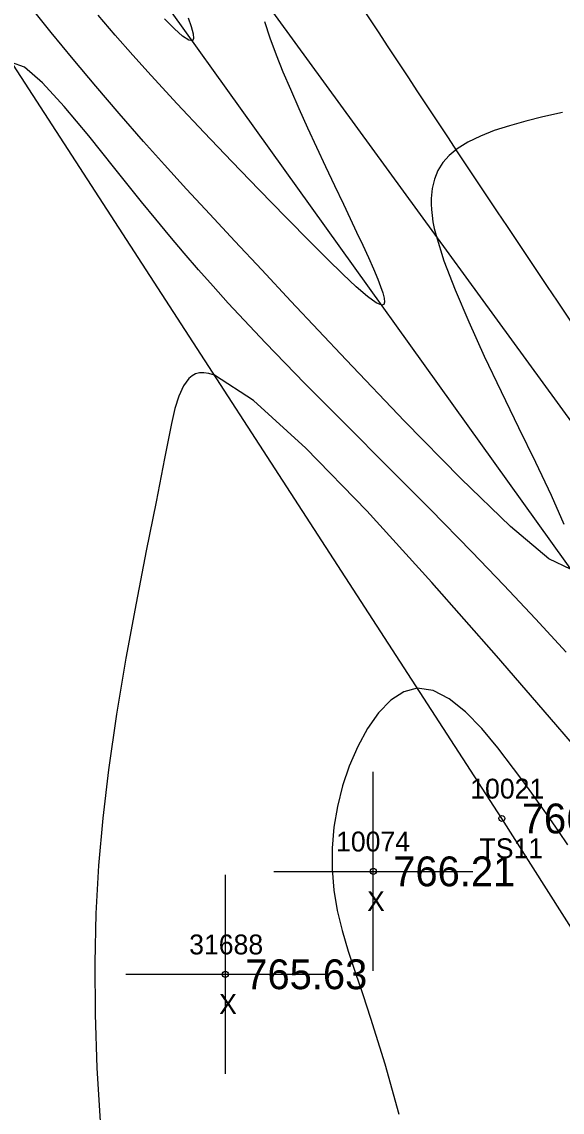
# Model space of a CAD drawing. Extents: x 1376587 to 1378239, y 1000335 to 1003031.
# Drawn here: x 1377991.7 to 1378018.9, y 1000532.4 to 1000587.3 of the extents above; entities that cross this region are included whole.
import ezdxf

# ---------------------------------------------------------------- set-up
doc = ezdxf.new("R2010")
doc.units = 0
for name, color, linetype in [('RD_DTM_BkLn1', 7, 'Continuous'), ('RD_DTM_BkLn2', 7, 'Continuous'), ('RD_DTM_BkLn_txCode', 7, 'Continuous'), ('RD_DTM_Major1', 7, 'Continuous'), ('RD_DTM_Minor1', 7, 'Continuous'), ('RD_EX_H2O', 7, 'Continuous'), ('RD_EX_Misc', 7, 'Continuous'), ('RD_EX_Misc_txCode', 7, 'Continuous'), ('RD_EX_Road', 7, 'Continuous'), ('RD_EX_TX_Misc_ELEV', 7, 'Continuous'), ('RD_SMD_Locator', 7, 'Continuous')]:
    doc.layers.add(name, color=color, linetype=linetype)

msp = doc.modelspace()

# ---------------------------------------------------------------- linework, layer by layer
at = {"layer": 'RD_DTM_BkLn1'}
msp.add_spline([(1378169.212, 1000387.103), (1378131.506, 1000434.744), (1378095.477, 1000481.988), (1378063.033, 1000526.867), (1378030.177, 1000574.233), (1377998.011, 1000622.539), (1377965.721, 1000673.201), (1377936, 1000721.493), (1377904.113, 1000773.429), (1377890.868, 1000795.129)], degree=3, dxfattribs=at)
at = {"layer": 'RD_DTM_BkLn2'}
for points in [[(1378152.795, 1000376.442), (1378153.623, 1000378.891), (1378133.341, 1000407.77), (1378106.208, 1000444.47), (1378079.422, 1000481.908), (1378052.603, 1000518.078), (1378027.38, 1000556.138), (1377999.887, 1000593.901), (1377975.443, 1000634.683), (1377966.188, 1000647.973)], [(1378152.458, 1000376.254), (1378150.255, 1000376.168), (1378128.245, 1000403.35), (1378101.014, 1000439.163), (1378072.773, 1000477.242), (1378039.24, 1000510.344), (1378015.855, 1000547.194), (1377989.301, 1000588.148), (1377962.727, 1000626.954), (1377952.76, 1000642.197)]]:
    msp.add_lwpolyline(points, dxfattribs=at)
at = {"layer": 'RD_DTM_Major1'}
msp.add_lwpolyline([(1378020.131, 1000550.114), (1378018.569, 1000551.921), (1378015.582, 1000555.372), (1378012.335, 1000559.066), (1378009.061, 1000562.665), (1378005.992, 1000565.828), (1378003.361, 1000568.216), (1378001.399, 1000569.489), (1378001.121, 1000569.577), (1378000.873, 1000569.616), (1378000.651, 1000569.608), (1378000.453, 1000569.555), (1378000.276, 1000569.46), (1378000.116, 1000569.325), (1377999.842, 1000568.95), (1377999.613, 1000568.44), (1377999.417, 1000567.809), (1377999.241, 1000567.067), (1377999.07, 1000566.227), (1377998.893, 1000565.301), (1377998.464, 1000563.114), (1377997.977, 1000560.665), (1377997.463, 1000558.023), (1377996.953, 1000555.258), (1377996.478, 1000552.439), (1377996.07, 1000549.634), (1377995.785, 1000547.215), (1377995.576, 1000544.82), (1377995.442, 1000542.406), (1377995.384, 1000539.931), (1377995.401, 1000537.355), (1377995.493, 1000534.634), (1377995.677, 1000531.698)], dxfattribs=at)
at = {"layer": 'RD_DTM_Minor1'}
for points in [[(1378019.341, 1000559.714), (1378018.219, 1000560.254), (1378016.287, 1000561.879), (1378013.785, 1000564.289), (1378010.951, 1000567.183), (1378008.027, 1000570.26), (1378005.249, 1000573.219), (1378003.777, 1000574.789), (1378002.422, 1000576.237), (1378001.166, 1000577.585), (1377999.993, 1000578.856), (1377998.886, 1000580.071), (1377997.83, 1000581.251), (1377996.608, 1000582.65), (1377995.43, 1000584.031), (1377994.294, 1000585.394), (1377993.195, 1000586.739), (1377992.128, 1000588.068)], [(1378003.917, 1000587.291), (1378004.189, 1000586.459), (1378004.502, 1000585.612), (1378004.847, 1000584.752), (1378005.218, 1000583.877), (1378005.64, 1000582.914), (1378006.079, 1000581.942), (1378006.528, 1000580.967), (1378006.982, 1000579.996), (1378007.436, 1000579.036), (1378007.884, 1000578.094), (1378008.223, 1000577.382), (1378008.549, 1000576.692), (1378008.856, 1000576.032), (1378009.14, 1000575.411), (1378009.393, 1000574.836), (1378009.61, 1000574.316), (1378009.752, 1000573.948), (1378009.861, 1000573.629), (1378009.929, 1000573.366), (1378009.949, 1000573.17), (1378009.915, 1000573.048), (1378009.819, 1000573.01), (1378009.532, 1000573.131), (1378009.095, 1000573.453), (1378008.528, 1000573.946), (1378007.853, 1000574.581), (1378007.091, 1000575.328), (1378006.262, 1000576.156), (1378004.987, 1000577.446), (1378003.647, 1000578.817), (1378002.271, 1000580.242), (1378000.889, 1000581.694), (1377999.529, 1000583.147), (1377998.221, 1000584.572), (1377997.302, 1000585.596), (1377996.415, 1000586.6), (1377995.548, 1000587.596)], [(1378000.076, 1000587.477), (1378000.231, 1000587.027), (1378000.328, 1000586.672), (1378000.353, 1000586.427), (1378000.296, 1000586.306), (1378000.108, 1000586.339), (1377999.799, 1000586.55), (1377999.386, 1000586.916), (1377998.887, 1000587.412)], [(1378019.093, 1000555.564), (1378017.54, 1000557.245), (1378015.957, 1000558.928), (1378014.341, 1000560.612), (1378012.245, 1000562.75), (1378010.125, 1000564.88), (1378008.016, 1000566.992), (1378005.953, 1000569.077), (1378003.968, 1000571.123), (1378002.096, 1000573.122), (1378001.336, 1000573.963), (1378000.597, 1000574.799), (1377999.874, 1000575.636), (1377999.16, 1000576.48), (1377998.451, 1000577.337), (1377997.739, 1000578.212), (1377996.398, 1000579.892), (1377995.085, 1000581.533), (1377993.854, 1000583.011), (1377992.759, 1000584.202), (1377991.856, 1000584.98), (1377991.198, 1000585.222)], [(1378018.895, 1000582.704), (1378017.906, 1000582.483), (1378017.053, 1000582.272), (1378016.238, 1000582.043), (1378015.473, 1000581.794), (1378014.771, 1000581.519), (1378014.143, 1000581.213), (1378013.601, 1000580.872), (1378013.209, 1000580.544), (1378012.889, 1000580.184), (1378012.639, 1000579.789), (1378012.458, 1000579.358), (1378012.344, 1000578.887), (1378012.294, 1000578.376), (1378012.293, 1000578.104), (1378012.308, 1000577.82), (1378012.34, 1000577.521), (1378012.389, 1000577.206), (1378012.457, 1000576.872), (1378012.542, 1000576.519), (1378012.939, 1000575.242), (1378013.497, 1000573.779), (1378014.186, 1000572.17), (1378014.97, 1000570.455), (1378015.818, 1000568.674), (1378016.696, 1000566.866), (1378017.55, 1000565.113), (1378018.332, 1000563.463), (1378018.972, 1000562.007)], [(1378019.173, 1000545.873), (1378018.713, 1000546.536), (1378018.26, 1000547.188), (1378017.809, 1000547.829), (1378017.358, 1000548.462), (1378016.904, 1000549.089), (1378016.444, 1000549.711), (1378015.649, 1000550.745), (1378014.838, 1000551.714), (1378014.018, 1000552.557), (1378013.2, 1000553.218), (1378012.391, 1000553.637), (1378011.601, 1000553.755), (1378010.918, 1000553.572), (1378010.267, 1000553.145), (1378009.658, 1000552.515), (1378009.101, 1000551.725), (1378008.604, 1000550.817), (1378008.179, 1000549.833), (1378007.84, 1000548.829), (1378007.581, 1000547.799), (1378007.405, 1000546.753), (1378007.316, 1000545.696), (1378007.315, 1000544.636), (1378007.405, 1000543.58), (1378007.578, 1000542.572), (1378007.823, 1000541.558), (1378008.127, 1000540.525), (1378008.475, 1000539.456), (1378008.854, 1000538.336), (1378009.249, 1000537.149), (1378009.961, 1000534.848), (1378010.68, 1000532.318)]]:
    msp.add_lwpolyline(points, dxfattribs=at)
at = {"layer": 'RD_EX_H2O'}
msp.add_lwpolyline([(1378150.92, 1000378.554), (1378129.931, 1000405.361), (1378103.429, 1000442.377), (1378075.971, 1000479.612), (1378048.045, 1000515.879), (1378023.997, 1000553.212), (1377996.392, 1000591.758), (1377970.527, 1000631.657), (1377963.482, 1000646.08)], dxfattribs=at)
at = {"layer": 'RD_EX_Misc'}
for p, q in [((1378009.39, 1000539.533), (1378009.39, 1000549.533)), ((1378004.39, 1000544.533), (1378014.39, 1000544.533)), ((1378001.951, 1000534.356), (1378001.951, 1000544.356)), ((1377996.951, 1000539.356), (1378006.951, 1000539.356))]:
    msp.add_line(p, q, dxfattribs=at)
at = {"layer": 'RD_EX_Road'}
for points in [[(1378177.15, 1000392.854), (1378139.733, 1000441.521), (1378104.671, 1000487.69), (1378071.786, 1000533.085), (1378038.454, 1000579.804), (1378007.554, 1000627.96), (1377974.27, 1000678.859), (1377944.465, 1000727.117), (1377913.028, 1000778.581), (1377899.668, 1000800.294)], [(1378161.362, 1000381.162), (1378123.914, 1000428.538), (1378087.578, 1000476.324), (1378055.075, 1000520.944), (1378021.673, 1000568.713), (1377989.952, 1000617.081), (1377957.327, 1000668.378), (1377927.534, 1000716.552), (1377895.409, 1000768.824), (1377883.752, 1000788.501)]]:
    msp.add_spline(points, degree=3, dxfattribs=at)
at = {"layer": 'RD_SMD_Locator'}
for centre in [(1378015.855, 1000547.194), (1378009.39, 1000544.533), (1378001.951, 1000539.356)]:
    msp.add_circle(centre, 0.15, dxfattribs=at)

# ---------------------------------------------------------------- texts
at = {"layer": 'RD_DTM_BkLn_txCode'}
for s, p in [('10021', (1378014.264, 1000548.194)), ('TS11', (1378014.729, 1000545.194))]:
    msp.add_text(s, height=1, dxfattribs=at).set_placement(p)
at = {"layer": 'RD_EX_Misc_txCode'}
for s, p in [('10074', (1378007.516, 1000545.533)), ('X', (1378009.075, 1000542.533)), ('31688', (1378000.132, 1000540.356)), ('X', (1378001.636, 1000537.356))]:
    msp.add_text(s, height=1, dxfattribs=at).set_placement(p)
at = {"layer": 'RD_EX_TX_Misc_ELEV'}
for s, p in [('766.42', (1378016.855, 1000546.444)), ('766.21', (1378010.39, 1000543.783)), ('765.63', (1378002.951, 1000538.606))]:
    msp.add_text(s, height=1.5, dxfattribs=at).set_placement(p)

doc.saveas('drawing.dxf')
